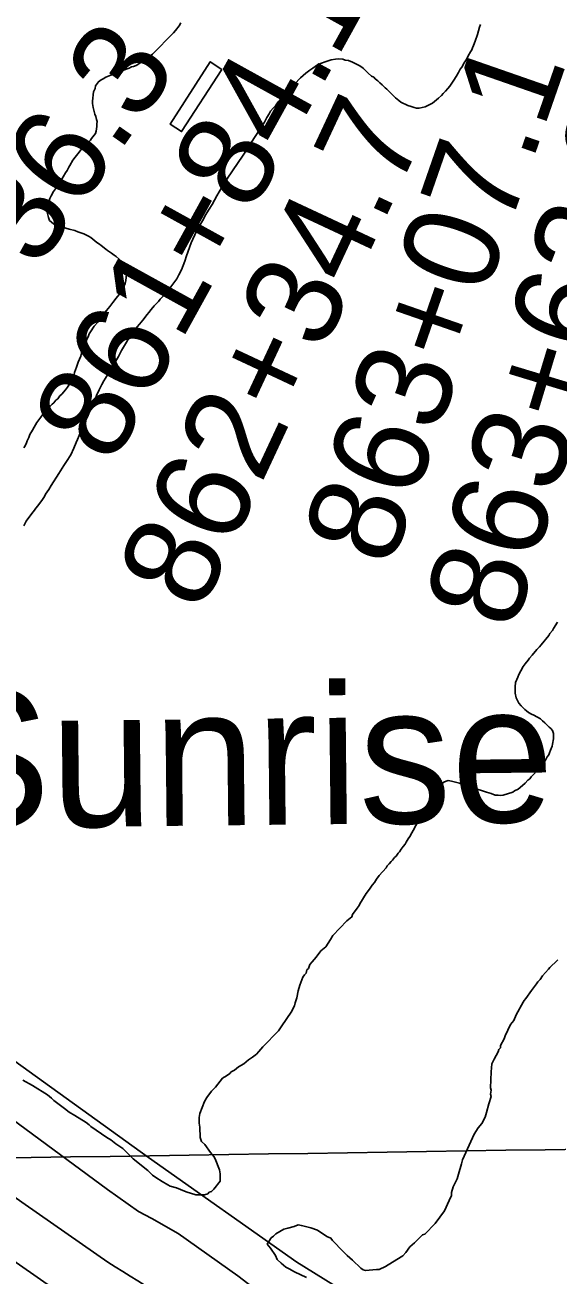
# Model space of a CAD drawing. Extents: x 3823584 to 3861785, y 301729 to 327625.
# Drawn here: x 3840866 to 3841424, y 319352 to 320663 of the extents above; entities that cross this region are included whole.
import ezdxf

# ---------------------------------------------------------------- set-up
doc = ezdxf.new("R2010")
doc.units = 0
for name, color, linetype in [('V-BLDG-OTLN', 7, 'Continuous'), ('V-GRID-MAJR', 7, 'Continuous'), ('V-ROAD-CNTR', 7, 'Continuous'), ('V-SITE-VEGE', 7, 'Continuous'), ('V-SURV-IDEN', 7, 'Continuous'), ('V-TOPO-GNAM-IDEN', 7, 'Continuous'), ('V-TOPO-SHOR', 7, 'Continuous')]:
    doc.layers.add(name, color=color, linetype=linetype)

msp = doc.modelspace()

# ---------------------------------------------------------------- linework, layer by layer
at = {"layer": 'V-BLDG-OTLN'}
msp.add_lwpolyline([(3841072.631, 320616.211), (3841030.432, 320550.968), (3841018.228, 320558.86100000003), (3841060.427, 320624.106)], close=True, dxfattribs=at)
at = {"layer": 'V-GRID-MAJR'}
msp.add_spline([(3827642.978, 319275.864), (3832951.406, 319355.783), (3838259.823, 319436.473), (3843568.228, 319517.936), (3848876.6210000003, 319600.17), (3854185.002, 319683.177), (3859493.3710000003, 319766.956), (3859493.372, 319766.956)], degree=3, dxfattribs=at)
at = {"layer": 'V-ROAD-CNTR'}
for points in [[(3838676.193608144, 320972.2010302), (3839296.088368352, 320545.2458841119), (3839628.872702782, 320309.8463549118), (3840049.7998609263, 320004.949964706), (3840549.2828619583, 319649.92367475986), (3840866.3282278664, 319427.0671204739), (3840952.9270546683, 319366.601241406)], [(3840964.6750311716, 319291.40339180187), (3840446.921066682, 319651.98867063), (3839584.5477914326, 320257.38645983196), (3839252.111456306, 320498.3529778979), (3838949.074062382, 320708.62955734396), (3838708.6275432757, 320880.458213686)]]:
    msp.add_lwpolyline(points, dxfattribs=at)
msp.add_spline([(3840952.9270546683, 319366.601241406), (3841078.607803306, 319288.098398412), (3841214.8715307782, 319204.9595646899), (3841372.5552154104, 319126.0757224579), (3841522.38991574, 319055.3248639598)], degree=3, dxfattribs=at)
at = {"layer": 'V-SITE-VEGE'}
for points in [[(3841029.464, 320664.956), (3841027.989, 320661.939), (3841023.828, 320656.792), (3841021.747, 320654.37), (3841000.009, 320632.241), (3840993.4450000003, 320627.076), (3840982.687, 320620.367), (3840979.994, 320619.14400000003), (3840977.895, 320618.822), (3840975.503, 320617.598), (3840973.406, 320616.678), (3840967.716, 320614.52400000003), (3840965.023, 320613.299), (3840961.427, 320612.363), (3840950.947, 320608.064), (3840948.258, 320606.237), (3840946.165, 320605.318), (3840943.179, 320603.186), (3840940.2120000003, 320598.955), (3840939.636, 320596.243), (3840938.166, 320592.624), (3840937.0500000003, 320583.001), (3840937.074, 320580.295), (3840937.7090000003, 320576.39400000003), (3840938.338, 320573.396), (3840939.577, 320569.199), (3840940.501, 320566.805), (3840941.131, 320563.506), (3840941.75, 320561.407), (3840941.469, 320559.301), (3840941.4960000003, 320556.297), (3840940.9390000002, 320551.484), (3840940.06, 320549.074), (3840935.897, 320543.927), (3840934.713, 320542.117), (3840932.032, 320539.387), (3840930.5470000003, 320537.568), (3840924.889, 320531.809), (3840923.1070000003, 320529.39), (3840921.6180000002, 320527.875), (3840918.646, 320524.242), (3840916.273, 320520.916), (3840913.315, 320515.48), (3840912.13, 320513.668), (3840910.356, 320510.346), (3840908.576, 320507.925), (3840901.177, 320495.24), (3840899.098, 320492.516), (3840896.1350000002, 320488.28500000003), (3840893.468, 320483.753), (3840892.291, 320481.037), (3840891.125, 320477.121), (3840890.241, 320475.01), (3840889.376, 320470.795), (3840889.102, 320468.09), (3840890.669, 320460.891), (3840891.895, 320457.897), (3840896.1350000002, 320454.329), (3840898.5470000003, 320453.451), (3840902.463, 320452.283), (3840906.082, 320450.813), (3840909.094, 320449.938), (3840912.41, 320448.767), (3840918.433, 320447.319), (3840921.452, 320445.842), (3840925.669, 320444.679), (3840927.778, 320443.798), (3840932.608, 320441.435), (3840935.325, 320439.956), (3840937.443, 320438.474), (3840941.68, 320434.906), (3840944.4020000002, 320433.126), (3840945.917, 320431.639), (3840951.06, 320427.779), (3840952.576, 320426.29), (3840956.807, 320423.623), (3840959.528, 320421.545), (3840961.644, 320420.06200000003), (3840964.974, 320417.385), (3840968.005, 320414.41000000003), (3840970.737, 320411.428), (3840971.6550000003, 320409.634), (3840972.582, 320406.637), (3840972.632, 320401.229), (3840971.786, 320394.913), (3840971.2120000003, 320391.902)], [(3841199.575, 320626.816), (3841201.987, 320625.935), (3841205.2970000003, 320625.366), (3841209.52, 320623.60000000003), (3841213.745, 320621.534), (3841216.46, 320620.356), (3841219.1780000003, 320618.579), (3841220.997, 320617.092), (3841225.846, 320612.328), (3841229.4820000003, 320609.056), (3841231.896, 320607.876), (3841233.412, 320606.387), (3841236.1380000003, 320604.007), (3841238.259, 320601.922), (3841240.682, 320599.842), (3841243.713, 320596.864), (3841245.5300000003, 320595.377), (3841254.623, 320586.444), (3841257.955, 320583.47000000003), (3841260.372, 320581.987), (3841267.615, 320578.446), (3841271.2320000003, 320577.279), (3841274.247, 320576.103), (3841276.6550000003, 320575.52400000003), (3841279.361, 320575.548), (3841285.656, 320577.107), (3841289.248, 320578.641), (3841293.436, 320580.783), (3841299.699, 320585.946), (3841302.974, 320588.979), (3841304.465, 320590.79600000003), (3841307.146, 320593.224), (3841309.524, 320596.249), (3841311.6040000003, 320598.672), (3841315.754, 320605.021), (3841318.123, 320608.648), (3841320.792, 320612.877), (3841322.561, 320616.5), (3841324.046, 320618.616), (3841326.71, 320623.148), (3841329.377, 320627.377), (3841330.8510000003, 320630.396), (3841333.217, 320634.623), (3841334.702, 320636.74), (3841335.2830000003, 320638.848), (3841336.465, 320641.262), (3841338.2260000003, 320645.784), (3841340.5670000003, 320652.717), (3841341.734, 320656.635), (3841342.603, 320660.24700000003), (3841343.778, 320663.262)], [(3840873.312, 320150.945), (3840876.2830000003, 320154.576), (3840877.469, 320156.39), (3840879.5500000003, 320158.813), (3840884.596, 320165.768), (3840886.673, 320168.793), (3840887.853, 320171.205), (3840891.115, 320176.043), (3840893.48, 320180.27400000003), (3840901.779, 320192.965), (3840906.815, 320201.123), (3840909.7830000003, 320205.356), (3840914.227, 320212.30700000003), (3840917.471, 320219.249), (3840919.8200000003, 320225.279), (3840921.296, 320228.295), (3840923.058, 320232.819), (3840924.827, 320236.44), (3840926.007, 320239.156), (3840928.944, 320246.693), (3840931.305, 320251.522), (3840935.129, 320260.572), (3840936.9020000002, 320263.892), (3840938.67, 320267.814), (3840941.316, 320274.447), (3840943.964, 320280.481), (3840946.622, 320285.914), (3840948.989, 320289.842), (3840950.468, 320292.558), (3840956.987, 320302.832), (3840959.938, 320308.569), (3840964.083, 320315.518), (3840967.3310000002, 320321.856), (3840972.664, 320330.317), (3840973.844, 320332.731), (3840976.2260000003, 320335.457), (3840977.715, 320336.973), (3840979.785, 320340.598), (3840981.5670000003, 320343.016), (3840983.937, 320346.643), (3840986.316, 320349.369), (3840989.585, 320353.604), (3840992.262, 320356.63300000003), (3840994.041, 320359.054), (3840996.421, 320361.78), (3840998.203, 320364.199), (3841000.284, 320366.619), (3841001.469, 320368.436), (3841003.554, 320370.556), (3841006.237, 320372.985), (3841008.019, 320375.403), (3841009.805, 320377.224), (3841012.781, 320380.554), (3841014.863, 320382.678), (3841020.211, 320389.637), (3841025.556, 320396.895), (3841027.319, 320401.118), (3841030.279, 320406.254), (3841033.8030000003, 320415.298), (3841035.556, 320420.723), (3841040.541, 320434.588), (3841042.012, 320438.207), (3841044.373, 320442.735), (3841046.143, 320446.657), (3841047.619, 320449.375), (3841050.284, 320453.907), (3841053.241, 320459.343), (3841055.0100000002, 320462.963), (3841059.156, 320469.912), (3841062.418, 320474.748), (3841067.444, 320483.808), (3841072.179, 320491.963), (3841074.839, 320496.794), (3841079.879, 320504.352), (3841081.661, 320506.77), (3841084.327, 320511.001), (3841099.454, 320533.07300000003), (3841103.007, 320538.813), (3841117.235, 320560.874), (3841119.895, 320565.708), (3841122.265, 320569.634), (3841123.741, 320572.351), (3841126.416, 320575.681), (3841128.798, 320578.106), (3841131.765, 320582.339), (3841135.935, 320586.583), (3841140.992, 320592.338), (3841143.969, 320595.07), (3841148.727, 320600.821), (3841154.9790000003, 320607.186), (3841160.644, 320612.044), (3841164.822, 320615.38800000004), (3841167.808, 320617.518), (3841170.497, 320619.044), (3841172.8850000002, 320620.868), (3841176.176, 320622.4), (3841181.8680000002, 320624.555), (3841187.262, 320626.105), (3841191.761, 320627.043), (3841194.463, 320627.371), (3841199.575, 320626.816)], [(3840971.2120000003, 320391.902), (3840969.15, 320387.378), (3840966.789, 320382.547), (3840961.734, 320376.491), (3840958.171, 320371.952), (3840955.203, 320367.719), (3840949.85, 320361.663), (3840948.664, 320359.849), (3840942.43, 320351.38), (3840938.86, 320347.141), (3840934.7090000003, 320341.093), (3840933.525, 320338.982), (3840932.352, 320335.967), (3840931.17, 320333.548), (3840929.998, 320330.235), (3840927.342, 320324.803), (3840925.292, 320318.77400000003), (3840924.719, 320315.766), (3840922.071, 320309.431), (3840920.897, 320306.416), (3840920.313, 320304.30700000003), (3840919.14, 320301.292), (3840918.261, 320298.581), (3840917.68, 320296.471), (3840915.91, 320292.85000000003), (3840914.147, 320288.627), (3840910.5870000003, 320283.188), (3840908.511, 320280.464), (3840904.642, 320275.922), (3840902.856, 320274.103), (3840900.481, 320271.078), (3840898.691, 320269.559), (3840896.311, 320266.835), (3840894.824, 320265.317), (3840892.139, 320262.89), (3840886.491, 320256.228), (3840884.705, 320254.41000000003), (3840882.626, 320251.688), (3840880.846, 320248.968), (3840878.768, 320246.244), (3840875.806, 320241.411), (3840874.0330000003, 320238.089), (3840871.3680000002, 320233.559), (3840870.1950000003, 320230.542), (3840868.421, 320227.22000000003), (3840867.84, 320225.113), (3840866.367, 320221.793), (3840864.88, 320219.677)], [(3840865.0130000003, 320137.95), (3840867.375, 320142.777), (3840873.312, 320150.945)], [(3841424.502, 320037.19), (3841420.355, 320030.545), (3841419.173, 320028.429), (3841416.495, 320025.4), (3841415.313, 320023.287), (3841407.289, 320013.298), (3841405.505, 320011.179), (3841402.824, 320008.451), (3841397.772, 320002.397), (3841395.093, 319999.368), (3841393.61, 319997.25)], [(3841393.61, 319997.25), (3841390.639, 319993.617), (3841388.562, 319990.594), (3841385.9, 319986.064), (3841383.829, 319982.13800000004), (3841382.952, 319979.427), (3841380.599, 319973.99700000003), (3841380.036, 319969.48600000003), (3841380.1, 319962.576), (3841381.044, 319957.775), (3841382.879, 319954.18700000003), (3841384.099, 319952.094), (3841386.227, 319949.409), (3841390.168, 319945.538), (3841391.98, 319944.353), (3841394.1, 319942.569), (3841397.1210000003, 319940.793), (3841399.836, 319939.616), (3841406.484, 319935.767), (3841408.6040000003, 319933.685), (3841411.325, 319931.606), (3841415.872, 319927.139), (3841417.39, 319925.65), (3841419.21, 319923.563), (3841420.1380000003, 319920.567), (3841420.1890000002, 319914.857), (3841419.3370000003, 319909.44), (3841418.754, 319907.333), (3841417.289, 319903.114), (3841416.116, 319900.097), (3841415.231, 319898.287), (3841413.748, 319895.87), (3841412.272, 319893.153), (3841411.086, 319891.338), (3841409.005, 319888.616), (3841407.5160000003, 319887.101), (3841405.437, 319884.377), (3841399.789, 319877.717), (3841396.809, 319874.985), (3841395.322, 319873.168), (3841393.532, 319871.651), (3841390.557, 319868.62), (3841385.1890000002, 319863.764), (3841383.102, 319862.242), (3841379.512, 319860.407), (3841377.72, 319859.191), (3841367.5330000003, 319855.793), (3841364.5330000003, 319855.465), (3841362.4250000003, 319855.748), (3841359.1180000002, 319856.018), (3841354.899, 319857.483), (3841350.078, 319858.943), (3841347.063, 319860.116), (3841344.6550000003, 319860.696), (3841341.3370000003, 319861.869), (3841333.202, 319864.499), (3841328.9820000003, 319865.965), (3841326.87, 319866.846), (3841323.862, 319867.42100000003), (3841321.748, 319868.304), (3841313.3140000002, 319870.63300000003), (3841309.704, 319871.2), (3841307.6070000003, 319870.582), (3841305.215, 319869.359), (3841300.4390000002, 319865.70900000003), (3841297.7600000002, 319862.983), (3841296.574, 319861.167), (3841294.4990000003, 319857.843), (3841292.423, 319854.82), (3841289.762, 319849.989), (3841288.882, 319847.576), (3841285.629, 319841.838), (3841282.379, 319835.499), (3841278.828, 319829.458), (3841273.2120000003, 319818.89), (3841271.734, 319816.473), (3841269.667, 319812.549), (3841267.884, 319810.131), (3841265.811, 319806.80700000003), (3841264.627, 319804.691), (3841262.546, 319802.271), (3841260.47, 319799.246), (3841258.991, 319796.53), (3841257.502, 319795.012), (3841255.426, 319791.99), (3841253.6380000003, 319790.472), (3841251.559, 319787.748), (3841250.068, 319786.233), (3841247.987, 319783.81), (3841245.9020000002, 319781.688), (3841244.717, 319779.876), (3841237.577, 319771.69800000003), (3841234.61, 319767.766), (3841232.535, 319764.442), (3841230.157, 319761.716), (3841228.083, 319758.392), (3841225.41, 319754.761), (3841223.9250000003, 319752.946), (3841217.413, 319742.072), (3841216.528, 319740.259), (3841214.447, 319737.537)], [(3841214.447, 319737.537), (3841209.4990000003, 319730.816), (3841208.688, 319728.305), (3841203.718, 319724.086), (3841188.8310000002, 319708.931), (3841186.365, 319704.735), (3841181.423, 319697.177), (3841176.455, 319692.961), (3841171.507, 319686.239), (3841167.378, 319681.197), (3841164.898, 319678.67), (3841163.268, 319674.481), (3841161.611, 319672.798), (3841160.806, 319669.452), (3841159.149, 319667.766), (3841157.507, 319665.249), (3841154.242, 319656.873), (3841152.6240000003, 319651.015), (3841151.023, 319643.489), (3841149.401, 319638.467), (3841148.596, 319635.121), (3841145.3170000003, 319628.416), (3841135.427, 319614.137), (3841132.136, 319609.101), (3841115.592, 319592.26), (3841111.466, 319587.216), (3841108.983, 319584.689), (3841104.84, 319581.314), (3841100.691, 319578.772), (3841095.72, 319574.555), (3841089.906, 319571.166), (3841085.765, 319567.787), (3841082.441, 319566.087), (3841080.786, 319564.406), (3841077.471, 319561.87200000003), (3841073.322, 319559.331), (3841065.8910000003, 319550.08400000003), (3841061.759, 319545.873), (3841056.808, 319539.152), (3841054.343, 319534.957), (3841049.448, 319522.395), (3841048.649, 319518.213), (3841048.703, 319512.37200000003), (3841049.575, 319508.208), (3841049.671, 319497.356), (3841051.377, 319493.199), (3841054.7460000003, 319489.889), (3841060.663, 319481.597), (3841064.04, 319477.454), (3841065.73, 319474.965), (3841070.008, 319463.318), (3841070.88, 319459.153), (3841070.948, 319451.643), (3841064.345, 319443.238), (3841061.865, 319440.71), (3841059.3680000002, 319439.854), (3841057.714, 319438.17100000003), (3841054.384, 319437.305), (3841045.202, 319437.223), (3841035.1550000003, 319440.473), (3841029.294, 319442.922), (3841025.105, 319444.555), (3841018.415, 319446.164), (3841015.896, 319447.811), (3841010.024, 319451.098), (3841003.311, 319455.21), (3840999.95, 319457.684), (3840994.897, 319462.647), (3840979.7630000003, 319475.031), (3840968.816, 319485.783), (3840961.259, 319490.723), (3840956.215, 319494.851), (3840952.021, 319497.317), (3840935.225, 319508.851), (3840933.539, 319510.506), (3840930.179, 319512.976), (3840918.427, 319520.386), (3840912.556, 319523.673), (3840907.511, 319527.8), (3840896.5870000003, 319536.049), (3840894.06, 319538.529), (3840889.86, 319541.83), (3840873.912, 319551.704), (3840863.846, 319557.457)], [(3841120.256, 319385.41000000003), (3841124.3680000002, 319392.124), (3841126.856, 319393.813), (3841129.338, 319396.343), (3841137.639, 319401.424), (3841141.805, 319402.29600000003), (3841148.465, 319404.025), (3841152.622, 319405.733), (3841155.969, 319404.928), (3841160.149, 319404.129), (3841166.006, 319402.51300000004), (3841172.705, 319400.07), (3841182.781, 319393.482), (3841186.967, 319391.849), (3841188.659, 319389.363), (3841199.613, 319377.775), (3841203.8200000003, 319373.63800000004), (3841209.71, 319368.684), (3841218.129, 319360.412), (3841220.648, 319358.766), (3841223.159, 319357.955), (3841234.8370000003, 319358.893), (3841237.342, 319358.915), (3841243.988, 319362.313), (3841251.461, 319366.554), (3841262.25, 319373.329), (3841265.559, 319376.696), (3841269.68, 319382.576), (3841274.648, 319386.793), (3841282.92, 319395.212), (3841285.416, 319396.07), (3841296.168, 319407.017), (3841306.0640000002, 319420.46), (3841310.973, 319431.353), (3841313.433, 319436.38300000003), (3841313.4020000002, 319439.721), (3841315.02, 319445.579), (3841319.1180000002, 319453.961), (3841320.742, 319458.985), (3841323.984, 319469.864), (3841324.781, 319474.044), (3841337.059, 319500.862), (3841341.173, 319507.576), (3841345.308, 319511.786), (3841348.5870000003, 319518.491), (3841350.2090000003, 319523.515), (3841352.634, 319532.717), (3841355.069, 319540.251), (3841354.213, 319542.748), (3841355.0100000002, 319546.928), (3841354.154, 319549.424), (3841354.838, 319566.12200000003), (3841355.597, 319574.476), (3841358.057, 319579.505), (3841362.161, 319587.054), (3841362.9760000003, 319589.565), (3841364.627, 319591.249), (3841364.6070000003, 319593.753), (3841368.719, 319600.467), (3841369.524, 319603.813), (3841375.262, 319615.548), (3841378.562, 319619.751), (3841381.0130000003, 319625.616), (3841388.404, 319639.037), (3841389.59, 319640.847), (3841391.3740000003, 319642.969), (3841397.311, 319651.134), (3841399.3880000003, 319654.157), (3841402.355, 319658.089), (3841403.84, 319660.207), (3841406.22, 319662.933), (3841408.89, 319666.56200000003), (3841415.139, 319673.529), (3841416.325, 319675.344), (3841418.111, 319677.162), (3841422.284, 319680.806), (3841424.967, 319683.233)], [(3841161.461, 319350.72500000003), (3841148.8910000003, 319356.456), (3841143.019, 319359.741), (3841139.666, 319361.379), (3841134.62, 319365.50800000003), (3841130.412, 319369.643), (3841128.7060000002, 319373.8), (3841123.631, 319381.267), (3841120.256, 319385.41000000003)]]:
    msp.add_lwpolyline(points, dxfattribs=at)
at = {"layer": 'V-TOPO-SHOR'}
for points in [[(3841143.455, 319310.843), (3841089.316, 319352.409), (3841026.879, 319396.656), (3840999.168, 319412.262), (3840985.315, 319419.72000000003), (3840952.7090000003, 319442.867), (3840809.7660000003, 319547.743), (3840668.9250000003, 319649.193), (3840664.776, 319650.532), (3840659.257, 319651.173), (3840655.853, 319646.317), (3840652.427, 319644.218), (3840649.65, 319646.262), (3840648.904, 319652.45900000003), (3840649.5330000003, 319659.359), (3840648.8000000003, 319664.178), (3840639.088, 319670.983), (3840529.565, 319738.936), (3840501.8170000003, 319758.679), (3840449.0870000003, 319796.808), (3840317.9620000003, 319890.76300000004), (3840233.3140000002, 319952.043), (3840061.984, 320071.142), (3839856.644, 320216.13)], [(3839985.827, 320184.88800000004), (3840132.8680000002, 320084.186), (3840283.404, 319977.99700000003), (3840505.36, 319824.885), (3840557.381, 319788.815), (3840697.503, 319690.806), (3840995.835, 319476.339), (3841151.227, 319366.749), (3841199.058, 319336.846), (3841264.855, 319302.28), (3841314.68, 319280.667), (3841429.52, 319234.821), (3841461.387, 319217.184), (3841495.998, 319200.949), (3841624.014, 319146.259), (3841829.4760000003, 319064.691), (3842024.572, 318985.786), (3842104.832, 318952.727), (3842146.398, 318929.663), (3842160.916, 318924.967), (3842162.2490000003, 318924.514), (3842190.647, 318914.893), (3842404.448, 318825.817)]]:
    msp.add_lwpolyline(points, dxfattribs=at)

# ---------------------------------------------------------------- texts
at = {"layer": 'V-SURV-IDEN'}
for s, height, rotation, p in [('861+84.1', 100.00000000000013, 61.08755117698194, (3840957.513810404, 320199.79501241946)), ('861+36.3', 100.00000000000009, 55.03796577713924, (3840705.9461647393, 320158.2955824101)), ('863+07.1', 100.00000000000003, 70.81863364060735, (3841249.676586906, 320092.41184278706)), ('862+34.7', 100.00000000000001, 64.97014642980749, (3841050.538893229, 320045.6450491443)), ('863+63.3', 99.99999999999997, 73.13700363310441, (3841379.32930581, 320026.55994064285))]:
    msp.add_text(s, height=height, rotation=rotation, dxfattribs=at).set_placement(p)
at = {"layer": 'V-TOPO-GNAM-IDEN'}
msp.add_text('Sunrise', height=144.9997119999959, rotation=0.6162221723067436, dxfattribs=at).set_placement((3840764.045665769, 319820.93258342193))

doc.saveas('drawing.dxf')
